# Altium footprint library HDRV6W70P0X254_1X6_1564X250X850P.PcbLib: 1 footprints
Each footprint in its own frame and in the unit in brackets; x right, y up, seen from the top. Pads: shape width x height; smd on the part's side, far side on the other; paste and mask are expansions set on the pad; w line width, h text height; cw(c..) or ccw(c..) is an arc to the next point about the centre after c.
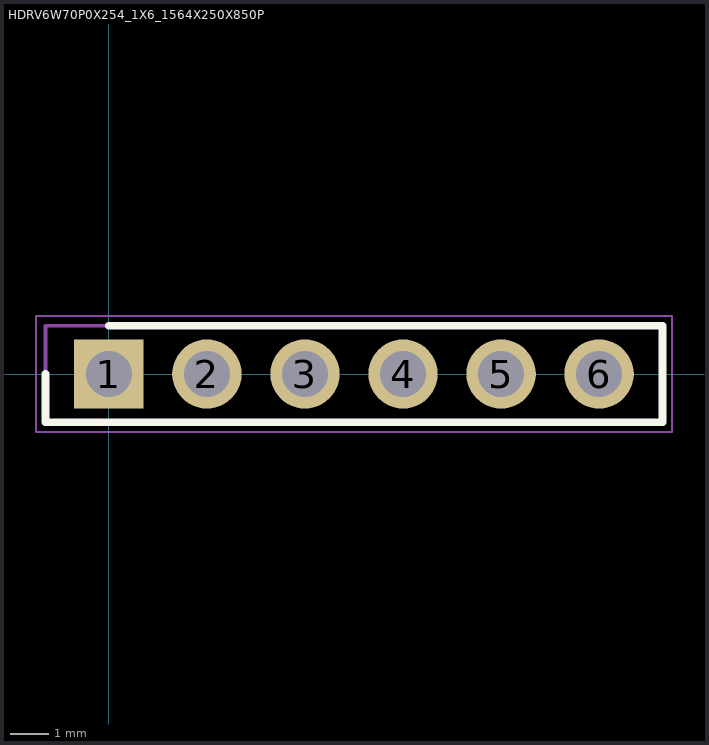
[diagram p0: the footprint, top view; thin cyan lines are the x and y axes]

## HDRV6W70P0X254_1X6_1564X250X850P [mm]
pads (6):
  rect 1.8x1.8 / inner round 1.8 / far side rect 1.8x1.8 hole 1.2: 1(0,0)
  round 1.8 hole 1.2: 2(2.54,0) 3(5.08,0) 4(7.62,0) 5(10.16,0) 6(12.7,0)
Top Overlay:
  lines w0.2: -1.645,0 -1.645,-1.25 14.345,-1.25 14.345,1.25 0,1.25
Mechanical 15:
  lines w0.1: -1.645,-1.25 14.345,-1.25 14.345,1.25 -1.645,1.25 -1.645,-1.25
Mechanical 20:
  lines w0.05: -1.895,-1.5 14.595,-1.5 14.595,1.5 -1.895,1.5 -1.895,-1.5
